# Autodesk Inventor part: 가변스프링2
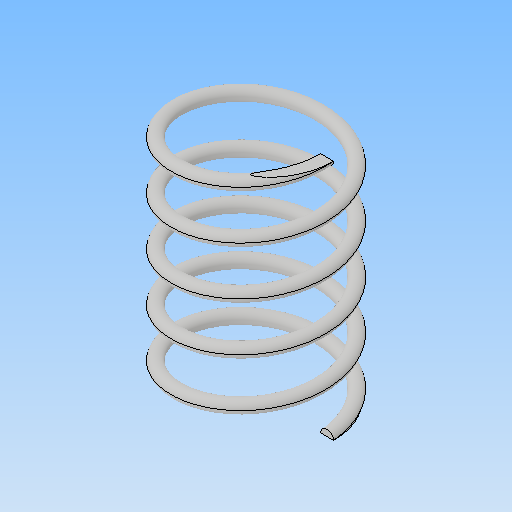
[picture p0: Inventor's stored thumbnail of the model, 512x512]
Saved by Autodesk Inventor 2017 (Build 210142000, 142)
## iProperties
Part Number: 가변스프링2
Material: 일반
Document SubType Name: Modeling
Designer: MRC
Density: 1 g/cm^3
Appearance: 기본값
Mass: 1.07319 g
Surface Area: 21.7273 cm^2
Volume: 1.07319 cm^3
Author: MRC
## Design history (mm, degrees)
sketch "스케치1"
  geometry: L1 (0, 0)-(0, 37.411); L2 (0, 0)-(11, 0); L3 (0, 37.411)-(11, 37.411); C1 r 1 at (11, 0)
  constraints: 6 end point, 2 horizontal, 1 centre point, 1 coincident, 1 vertical
  dimensions: "d0" = 37.4112 distance of L1.start L1.end (derived); "d1" = 11 distance of L1.end L3.end; "d2" = 11 distance of L1.start L2.end; "d3" = 2 diameter of C1
feature "코일1" sketch "스케치1" pitch "d4" = 10; turns "d6" = 5; dims "d5" = 37.4112 (= d0), "d7" = 0, angle "d8" = 90 deg, angle "d9" = 90 deg, "d10" = 0, "d11" = 0
sketch "스케치2"
  geometry: L1 (37.411, 15)-(0, 15); L2 (0, 15)-(0, -15); L3 (0, -15)-(37.411, -15); L4 (37.411, -15)-(37.411, 15); 2 further points
  constraints: 8 end point, 2 parallel, 1 coincident, 1 horizontal, 1 midpoint, 1 perpendicular
  dimensions: "d12" = 37.4112 distance of L2.end L3.end (= d0); "d13" = 30 distance of L3.end L1.start
extrude "돌출1" sketch "스케치2" stored distance "d14" = 0; taper "d15" = 0 deg
node "솔리드1"
